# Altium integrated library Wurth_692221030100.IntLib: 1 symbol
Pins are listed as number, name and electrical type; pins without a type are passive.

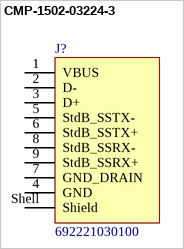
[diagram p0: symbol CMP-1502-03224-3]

## CMP-1502-03224-3
designator J?, comment 692221030100
Conn USB 3.0 Type B RCP 9 POS (1.75mm/2.5)mm/1.25mm Solder RA Thru-Hole 9 Terminal 1 Port Tray; Gender: Receptacle; USB Standard: USB 3.0; Insulation Resistance: 100MΩ; Voltage Rating: 30V; Current Rating: 250mA; Number of Contacts: 9; Contact Resistance: 50mΩ; Number of Ports: 1
footprint 692221030100 (USB 3.0 Type B Horizontal)
pins: 1 VBUS, 2 D-, 3 D+, 4 GND, 5 StdB_SSTX-, 6 StdB_SSTX+, 7 GND_DRAIN, 8 StdB_SSRX-, 9 StdB_SSRX+, Shell Shield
